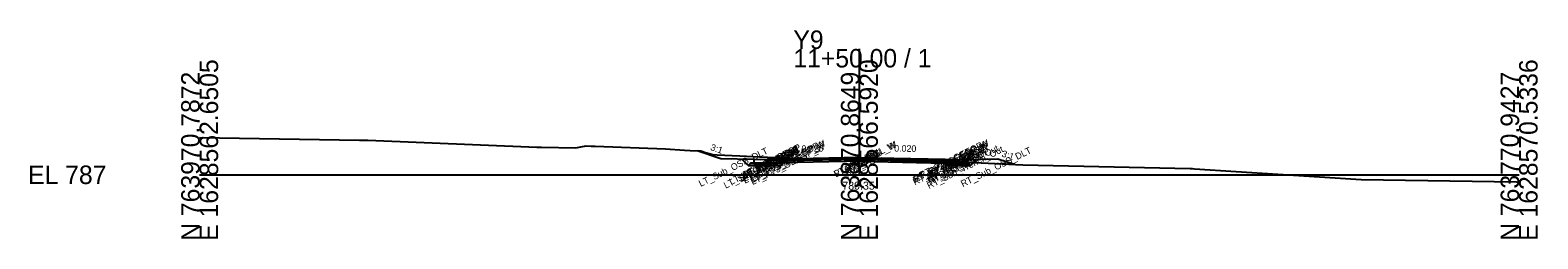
# Model space of a CAD drawing. Extents: x -26 to 203, y -10 to 6017.
# Drawn here: x -25.7 to 202.8, y 2990.3 to 3021.9 of the extents above; entities that cross this region are included whole.
import ezdxf

# ---------------------------------------------------------------- set-up
doc = ezdxf.new("R2010")
doc.units = 0
for name, color, linetype in [('Default', 7, 'Continuous'), ('Exist Cross Section Cell', 7, 'Continuous'), ('Exist XS Center Line Elevation Label', 7, 'Continuous'), ('Exist XS Ground Line', 7, 'Continuous'), ('Prop CMT Concrete Structures', 7, 'Continuous'), ('Prop CMT Pvmt Course 1', 7, 'Continuous'), ('Prop CMT Pvmt Course 1 Wedge', 7, 'Continuous'), ('Prop CMT Pvmt Course 2', 7, 'Continuous'), ('Prop CMT Pvmt Course 2 Wedge', 7, 'Continuous'), ('Prop CMT Pvmt Course 3', 7, 'Continuous'), ('Prop CMT Pvmt Surface', 7, 'Continuous'), ('Prop CMT Pvmt Surface Shoulder', 7, 'Continuous'), ('Prop CMT Pvmt Wedge Surface 1', 7, 'Continuous'), ('Prop CMT Pvmt Wedge Surface 2', 7, 'Continuous'), ('Prop CMT Pvmt Wedge Surface 3', 7, 'Continuous'), ('Prop CMT Shld Paved Course 1', 7, 'Continuous'), ('Prop CMT Shld Paved Course 2', 7, 'Continuous'), ('Prop CMT Shld Paved Course 3', 7, 'Continuous'), ('Prop CMT Slope Grass', 7, 'Continuous'), ('Prop CMT Subgrade Earthwork', 7, 'Continuous'), ('Prop XS SE Text', 7, 'Continuous'), ('Prop XS Side Slope Text', 7, 'Continuous'), ('Scratch_Level_0', 7, 'Continuous')]:
    doc.layers.add(name, color=color, linetype=linetype)

msp = doc.modelspace()

# ---------------------------------------------------------------- linework, layer by layer
at = {"layer": 'Exist Cross Section Cell'}
for p, q in [((100, 3000), (100, 3019.05)), ((0, 3000), (100, 3000)), ((100, 3000), (200, 3000))]:
    msp.add_line(p, q, dxfattribs=at)
at = {"layer": 'Exist XS Ground Line'}
msp.add_lwpolyline([(0, 3005.65), (24.25, 3005.25), (25.51, 3005.23), (51.11, 3004.19), (51.82, 3004.17), (57.04, 3004.06), (57.79, 3004.21), (58.59, 3004.38), (59.36, 3004.35), (59.93, 3004.33), (70.61, 3003.93), (73.5, 3003.74), (74.34, 3003.69), (75.6, 3003.63), (75.98, 3003.61), (76.68, 3003.4), (77.81, 3003.07), (78.45, 3003.04), (81.88, 3002.87), (84.85, 3002.73), (87.27, 3002.61), (89.12, 3002.52), (98.88, 3002.38), (100, 3002.35), (106.17, 3002.17), (115.34, 3001.96), (124.77, 3001.51), (150.14, 3000.94), (150.49, 3000.93), (150.82, 3000.92), (176.07, 2999.31), (199.58, 2998.92), (200, 2998.9)], dxfattribs=at)
at = {"layer": 'Prop CMT Concrete Structures'}
for points in [[(84, 3002.34), (84, 3001.76), (86, 3001.76)], [(86, 3002.34), (85, 3002.26), (84, 3002.34)], [(86, 3001.76), (86, 3002.34)], [(116, 3002.34), (116, 3001.76), (114, 3001.76)], [(114, 3002.34), (115, 3002.26), (116, 3002.34)], [(114, 3001.76), (114, 3002.34)]]:
    msp.add_lwpolyline(points, dxfattribs=at)
at = {"layer": 'Prop CMT Pvmt Course 1'}
for points in [[(100, 3002.62), (86, 3002.34)], [(86, 3002.09), (100, 3002.37)], [(86, 3002.34), (86, 3002.09)], [(100, 3002.62), (88.36, 3002.39)], [(88.36, 3002.26), (100, 3002.5)], [(88.36, 3002.39), (88.36, 3002.26)], [(100, 3002.5), (100, 3002.62)], [(100, 3002.37), (100, 3002.62)], [(100, 3002.62), (113, 3002.36)], [(100, 3002.5), (100, 3002.62)], [(100, 3002.62), (114, 3002.34)], [(100, 3002.37), (100, 3002.62)], [(113, 3002.24), (100, 3002.5)], [(114, 3002.09), (100, 3002.37)], [(113, 3002.36), (113, 3002.24)], [(114, 3002.34), (114, 3002.09)]]:
    msp.add_lwpolyline(points, dxfattribs=at)
at = {"layer": 'Prop CMT Pvmt Course 1 Wedge'}
for points in [[(91.26, 3002.32), (98.88, 3002.47)], [(100, 3002.37), (99.53, 3002.36), (98.88, 3002.38), (91.26, 3002.32)], [(98.88, 3002.47), (100, 3002.5)], [(100, 3002.5), (100, 3002.37)], [(100, 3002.5), (113, 3002.24)], [(100, 3002.37), (100, 3002.5)], [(113, 3002.11), (100, 3002.37)], [(113, 3002.24), (113, 3002.11)]]:
    msp.add_lwpolyline(points, dxfattribs=at)
at = {"layer": 'Prop CMT Pvmt Course 2'}
for points in [[(100, 3002.37), (86, 3002.09)], [(86, 3002.09), (86, 3001.76)], [(86, 3001.76), (88.36, 3001.81)], [(100, 3002.37), (114, 3002.09)], [(114, 3001.76), (113, 3001.78)], [(114, 3002.09), (114, 3001.76)]]:
    msp.add_lwpolyline(points, dxfattribs=at)
at = {"layer": 'Prop CMT Pvmt Course 2 Wedge'}
for points in [[(99.53, 3002.36), (100, 3002.37)], [(100, 3002.35), (99.53, 3002.36)], [(100, 3002.37), (100, 3002.35)], [(100, 3002.37), (113, 3002.11)], [(100, 3002.35), (100, 3002.37)], [(113, 3002.02), (100, 3002.35)], [(113, 3002.11), (113, 3002.02)]]:
    msp.add_lwpolyline(points, dxfattribs=at)
at = {"layer": 'Prop CMT Pvmt Course 3'}
msp.add_line((116, 3001.76), (116.5, 3001.76), dxfattribs=at)
for points in [[(88.36, 3001.81), (86, 3001.76)], [(86, 3001.76), (86, 3001.42)], [(86, 3001.42), (88.36, 3001.47)], [(113, 3001.78), (114, 3001.76)], [(114, 3001.42), (113, 3001.44)], [(114, 3001.76), (114, 3001.42)]]:
    msp.add_lwpolyline(points, dxfattribs=at)
at = {"layer": 'Prop CMT Pvmt Surface'}
for points in [[(100, 3002.62), (86, 3002.34)], [(100, 3002.62), (88.36, 3002.39)], [(100, 3002.62), (114, 3002.34)], [(100, 3002.62), (113, 3002.36)]]:
    msp.add_lwpolyline(points, dxfattribs=at)
at = {"layer": 'Prop CMT Pvmt Surface Shoulder'}
for points in [[(86, 3002.34), (86, 3002.34)], [(114, 3002.34), (114, 3002.34)]]:
    msp.add_lwpolyline(points, dxfattribs=at)
at = {"layer": 'Prop CMT Pvmt Wedge Surface 1'}
for points in [[(100, 3002.5), (88.36, 3002.26)], [(88.36, 3002.26), (88.36, 3002.39)], [(100, 3002.5), (113, 3002.24)], [(113, 3002.24), (113, 3002.36)]]:
    msp.add_lwpolyline(points, dxfattribs=at)
at = {"layer": 'Prop CMT Pvmt Wedge Surface 2'}
for points in [[(88.36, 3002.14), (88.36, 3002.39)], [(100, 3002.37), (88.36, 3002.14)], [(100, 3002.37), (100, 3002.62)], [(100, 3002.37), (100, 3002.62)], [(100, 3002.37), (100, 3002.62)], [(100, 3002.37), (100, 3002.62)], [(100, 3002.37), (113, 3002.11)], [(113, 3002.11), (113, 3002.36)]]:
    msp.add_lwpolyline(points, dxfattribs=at)
at = {"layer": 'Prop CMT Pvmt Wedge Surface 3'}
for points in [[(88.36, 3001.81), (88.36, 3002.39)], [(100, 3002.04), (88.36, 3001.81)], [(100, 3002.04), (113, 3001.78)], [(113, 3001.78), (113, 3002.36)]]:
    msp.add_lwpolyline(points, dxfattribs=at)
at = {"layer": 'Prop CMT Shld Paved Course 1'}
for points in [[(86, 3002.34), (86, 3002.34)], [(86, 3002.09), (86, 3002.34)], [(114, 3002.34), (114, 3002.34)], [(114, 3002.09), (114, 3002.34)]]:
    msp.add_lwpolyline(points, dxfattribs=at)
at = {"layer": 'Prop CMT Shld Paved Course 2'}
for p, q in [((84, 3001.76), (86, 3001.76)), ((116, 3001.76), (114, 3001.76))]:
    msp.add_line(p, q, dxfattribs=at)
for points in [[(86, 3001.76), (86, 3002.09)], [(114, 3001.76), (114, 3002.09)]]:
    msp.add_lwpolyline(points, dxfattribs=at)
at = {"layer": 'Prop CMT Shld Paved Course 3'}
for p, q in [((83.16, 3001.42), (86, 3001.42)), ((116.84, 3001.42), (114, 3001.42))]:
    msp.add_line(p, q, dxfattribs=at)
for points in [[(86, 3001.76), (84, 3001.76), (83.5, 3001.76), (83.16, 3001.42)], [(86, 3001.42), (86, 3001.76)], [(114, 3001.42), (114, 3001.76)], [(114, 3001.76), (116.5, 3001.76), (116.5, 3001.76), (116.84, 3001.42)]]:
    msp.add_lwpolyline(points, dxfattribs=at)
at = {"layer": 'Prop CMT Slope Grass'}
for points in [[(84, 3002.34), (79, 3002.44), (75.41, 3003.64)], [(116, 3002.34), (121, 3002.44), (123.64, 3001.56)]]:
    msp.add_lwpolyline(points, dxfattribs=at)
at = {"layer": 'Prop CMT Subgrade Earthwork'}
for p, q in [((83.16, 3001.42), (82.2, 3002.38)), ((86, 3001.42), (83.16, 3001.42)), ((88.36, 3001.47), (88.36, 3002.3)), ((113, 3002.02), (113, 3001.44)), ((114, 3001.42), (116.84, 3001.42)), ((116.84, 3001.42), (117.8, 3002.38))]:
    msp.add_line(p, q, dxfattribs=at)
for points in [[(88.36, 3001.47), (86, 3001.42)], [(113, 3001.44), (114, 3001.42)]]:
    msp.add_lwpolyline(points, dxfattribs=at)

# ---------------------------------------------------------------- texts
at = {"layer": 'Default'}
msp.add_text('-', height=0.0001, dxfattribs=at).set_placement((0, 3000))
at = {"layer": 'Exist Cross Section Cell'}
for s, p in [('Y9', (90, 3019.05)), ('11+50.00 / 1', (90, 3016.25)), ('EL 787', (-26, 2998.6))]:
    msp.add_text(s, height=2.8, dxfattribs=at).set_placement(p)
for s, p in [('E 1628562.6505', (2.8, 2990)), ('E 1628566.5920', (102.8, 2990)), ('E 1628570.5336', (202.8, 2990)), ('N 763970.7872', (0, 2990)), ('N 763870.8649', (100, 2990)), ('N 763770.9427', (200, 2990))]:
    msp.add_text(s, height=2.8, rotation=90, dxfattribs=at).set_placement(p)
at = {"layer": 'Exist XS Center Line Elevation Label'}
msp.add_text('789.35', height=1.2, dxfattribs=at).set_placement((97.42, 2997.75))
at = {"layer": 'Prop XS SE Text'}
for rotation, p in [(1.1458, (91.23, 3003.45)), (358.8542, (105.27, 3003.52))]:
    msp.add_text('0.020', height=1, rotation=rotation, dxfattribs=at).set_placement(p)
at = {"layer": 'Prop XS Side Slope Text'}
for p in [(77.34, 3003.76), (121.49, 3002.79)]:
    msp.add_text('3:1', height=1, rotation=341.5651, dxfattribs=at).set_placement(p)
at = {"layer": 'Scratch_Level_0'}
for s, p in [('LT_PV1_OEEOP_W', (83.93, 2998.93)), ('RT_PV2_OEEOP_W', (108.42, 2998.7)), ('RT_PV1_OEEOP_W', (108.52, 2998.88)), ('LT_Sub_OSS_DLT', (75.95, 2998.15)), ('LT_Sub_Trench_Out', (79.74, 2997.87)), ('LT_PS3_Shelf_Out', (80.57, 2998.45)), ('LT_PS3_OEOP', (82.08, 2998.97)), ('LT_PS2_OEOP', (82.42, 2999.31)), ('LT_PV2_OEOT', (82.64, 2999.29)), ('LT_PV3_OEOT', (82.64, 2998.96)), ('LT_Sub_OEOT', (82.66, 2998.64)), ('LT_PV1_OEOT', (82.75, 2999.6)), ('LT_PS1_OEOP', (82.79, 2999.62)), ('LT_PV2_OEEOP_W', (83.82, 2998.75)), ('LT_PV3_OEEOP_W', (83.82, 2998.42)), ('LT_PV1_OEEOP', (84.79, 2999.49)), ('RT_PV1_PGL_W', (96.41, 2999.59)), ('LT_PV1_PGL_W', (96.47, 2999.61)), ('PV2_PGL', (98.08, 3000.29)), ('PV3_PGL', (98.08, 2999.96)), ('PV1_PGL', (98.18, 3000.6)), ('RT_PV3_OEEOP_W', (108.42, 2998.37)), ('RT_PV1_OEEOP', (109.38, 2999.43)), ('RT_Sub_Trench_Out', (110.56, 2997.84)), ('RT_PV2_OEOT', (110.59, 2999.27)), ('RT_PV3_OEOT', (110.59, 2998.93)), ('RT_Sub_OEOT', (110.61, 2998.61)), ('RT_PV1_OEOT', (110.7, 2999.57)), ('RT_PS3_Shelf_Out', (110.71, 2998.43)), ('RT_PS1_OEOP', (110.73, 2999.59)), ('RT_PS2_OEOP', (110.88, 2999.28)), ('RT_PS3_OEOP', (111.22, 2998.94)), ('RT_Sub_OSS_DLT', (115.68, 2998.12)), ('Sub_PGL', (98.1, 2999.64))]:
    msp.add_text(s, height=1, rotation=26.5651, dxfattribs=at).set_placement(p)

doc.saveas('drawing.dxf')
